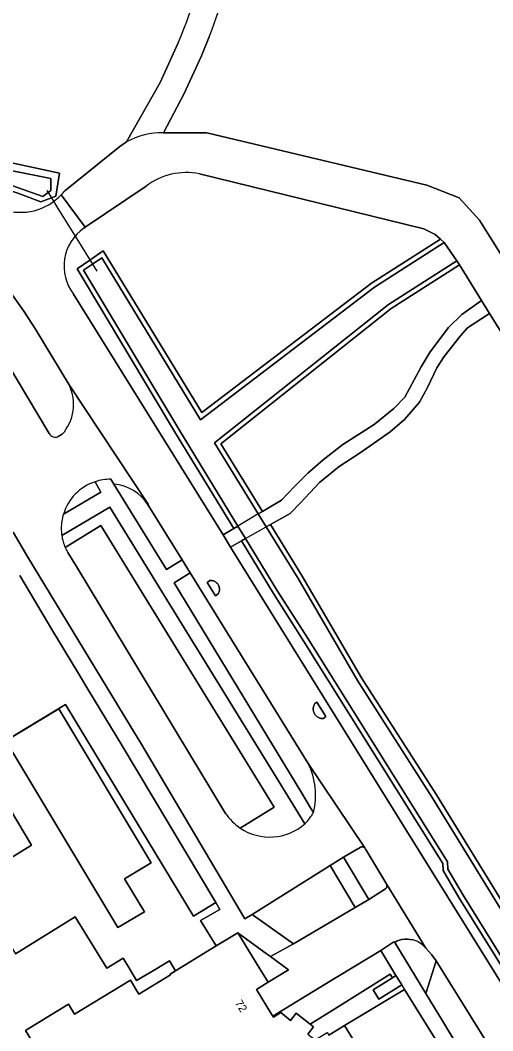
# Model space of a CAD drawing. Extents: x 158132 to 159664, y 385256 to 387218.
# Drawn here: x 158675.2 to 158734.3, y 386749.8 to 386876.1 of the extents above; entities that cross this region are included whole.
import ezdxf

# ---------------------------------------------------------------- set-up
doc = ezdxf.new("R2010")
doc.units = 0
for name, color, linetype in [('IMGEO_Berm_groen', 7, 'Continuous'), ('IMGEO_Dek', 7, 'Continuous'), ('IMGEO_Duiker', 7, 'Continuous'), ('IMGEO_Gemengd_bos', 7, 'Continuous'), ('IMGEO_Groenvoorziening', 7, 'Continuous'), ('IMGEO_Loofbos', 7, 'Continuous'), ('IMGEO_Oever', 7, 'Continuous'), ('IMGEO_Pand', 7, 'Continuous'), ('IMGEO_Pand_nummerreeks', 7, 'Continuous'), ('IMGEO_Parkeervlak_open', 7, 'Continuous'), ('IMGEO_Rijbaan_lokaal_gesloten', 7, 'Continuous'), ('IMGEO_Verkeerseiland_gesloten', 7, 'Continuous'), ('IMGEO_Voetpad_gesloten', 7, 'Continuous'), ('IMGEO_Voetpad_open', 7, 'Continuous'), ('IMGEO_Waterloop', 7, 'Continuous')]:
    doc.layers.add(name, color=color, linetype=linetype)

msp = doc.modelspace()

# ---------------------------------------------------------------- linework, layer by layer
at = {"layer": 'IMGEO_Berm_groen'}
msp.add_lwpolyline([(158718.49, 386772.28), (158718.35, 386772.52), (158718.33, 386772.55), (158718.32, 386772.58), (158718.3, 386772.61), (158718.28, 386772.65), (158718.25, 386772.67), (158718.23, 386772.7), (158718.2, 386772.72), (158718.17, 386772.74), (158718.14, 386772.76), (158718.11, 386772.78), (158718.07, 386772.79), (158718.04, 386772.8), (158718, 386772.81), (158717.96, 386772.81), (158717.93, 386772.81), (158717.89, 386772.81), (158717.85, 386772.8), (158717.82, 386772.79), (158717.78, 386772.78), (158717.75, 386772.76), (158717.72, 386772.74), (158717.69, 386772.72), (158715.6, 386771.51), (158718.77, 386766.24), (158720.86, 386767.56), (158720.89, 386767.59), (158720.92, 386767.62), (158720.94, 386767.65), (158720.96, 386767.68), (158720.98, 386767.72), (158721, 386767.75), (158721.01, 386767.79), (158721.02, 386767.83), (158721.02, 386767.87), (158721.03, 386767.91), (158721.03, 386767.95), (158721.02, 386767.99), (158721.01, 386768.03), (158721, 386768.07), (158720.99, 386768.1)], close=True, dxfattribs=at)
for points in [[(158724.29, 386761.18), (158723.94, 386761.23), (158723.6, 386761.26), (158723.25, 386761.26), (158722.83, 386761.21), (158722.58, 386761.15), (158722.28, 386761.04), (158722, 386760.84), (158725.88, 386754.49), (158727.18, 386758.58), (158726.58, 386759.37)], [(158726.58, 386759.37), (158725.88, 386760.15)]]:
    msp.add_lwpolyline(points, dxfattribs=at)
msp.add_arc((158723.16, 386757.71), 3.65, 41.8095, 71.8996, dxfattribs=at)
at = {"layer": 'IMGEO_Dek'}
msp.add_lwpolyline([(158702.4, 386812.87), (158703.36, 386811.3), (158705.94, 386812.76), (158704.94, 386814.39)], close=True, dxfattribs=at)
at = {"layer": 'IMGEO_Duiker'}
msp.add_lwpolyline([(158678.52, 386854.78), (158679.08, 386853.88), (158679.91, 386852.53), (158682.26, 386848.76), (158684.22, 386845.59), (158684.77, 386844.71)], dxfattribs=at)
at = {"layer": 'IMGEO_Gemengd_bos'}
for points in [[(158680.75, 386854.76), (158687.66, 386860.29), (158688.48, 386860.86), (158692.7, 386868.26), (158694.92, 386873.24)], [(158738.91, 386831.3), (158733.85, 386839.44), (158731.1, 386837.62), (158730.16, 386836.58), (158728.18, 386834.05), (158727.27, 386832.64), (158726.09, 386830.17), (158725.08, 386828.34), (158723.21, 386826.18), (158721.42, 386824.63), (158717.66, 386822.03), (158715.04, 386820.31), (158712.61, 386818.33), (158710.24, 386815.76), (158708.92, 386814.43), (158706.47, 386813.06), (158710.42, 386806.62), (158717.85, 386793.91), (158727.2, 386779.3), (158741.74, 386755.65)], [(158740.46, 386749.68), (158730.02, 386766.46), (158728.05, 386769.86), (158728, 386770.74), (158710.65, 386798.45), (158706.84, 386804.44), (158702.83, 386811.01), (158701.48, 386810.25), (158723.32, 386775.09), (158738.91, 386750), (158774.33, 386692.97)]]:
    msp.add_lwpolyline(points, dxfattribs=at)
for points in [[(158656.87, 386864.6), (158671.2, 386858.87), (158680.09, 386856.96), (158679.66, 386854.1), (158679.08, 386853.88), (158677.76, 386853.39), (158674.89, 386854.45), (158670.51, 386855.93), (158656.02, 386862.13), (158655.71, 386862.64), (158655.77, 386863.65)], [(158723.27, 386828.98), (158725.3, 386832.77), (158726.42, 386834.63), (158728.71, 386837.66), (158730.4, 386839.32), (158732.86, 386841.04), (158730.08, 386845.51), (158721.55, 386840.04), (158700.28, 386823.13), (158705.46, 386814.7), (158706.08, 386815.07), (158707.85, 386816.12), (158709.41, 386817.79), (158711.14, 386819.48), (158713.07, 386821.13), (158715.52, 386823.06), (158719.44, 386825.55), (158721.9, 386827.54)]]:
    msp.add_lwpolyline(points, close=True, dxfattribs=at)
for centre, radius, start, end in [((158644.17, 386895.43), 55.39, 336.384, 352.0933), ((158674.85, 386859.35), 7.48, 316.9831, 322.1116), ((158675.25, 386859.02), 6.96, 251.4012, 316.7563)]:
    msp.add_arc(centre, radius, start, end, dxfattribs=at)
at = {"layer": 'IMGEO_Groenvoorziening'}
for points in [[(158664.17, 386848.88), (158678.81, 386824.43)], [(158681.3, 386830.5), (158677.11, 386837.46), (158675.65, 386839.71), (158673.58, 386842.6)], [(158679.94, 386824.05), (158680.44, 386824.34)], [(158680.58, 386814.35), (158685.27, 386817.11), (158684.55, 386818.41)], [(158686.88, 386818.1), (158693.47, 386807.44), (158695.42, 386808.65), (158691.18, 386815.5)], [(158686.4, 386815.24), (158680.38, 386811.68)], [(158710.77, 386775.68), (158707.51, 386780.97), (158686.4, 386815.24)], [(158680.82, 386810.2), (158685.25, 386812.93), (158706.92, 386777.76), (158702.68, 386775.15)], [(158671.29, 386784.84), (158680.83, 386790.6), (158689.31, 386776.58), (158696.85, 386764.13), (158699.63, 386765.83), (158687.88, 386785.52), (158683.77, 386792.31), (158682.34, 386794.67), (158679.27, 386799.74), (158675.13, 386806.7)], [(158696.43, 386807.03), (158694.45, 386805.79), (158710.38, 386779.52), (158711.48, 386777.69), (158711.85, 386777.09)], [(158711.19, 386783.22), (158696.43, 386807.03)], [(158669.14, 386768.44), (158676.6, 386773.03), (158673.99, 386777.44)], [(158677.41, 386747.38), (158675.87, 386749.87), (158681.23, 386753.15), (158681.98, 386751.89), (158688.98, 386756.15), (158690.02, 386754.39), (158693.99, 386756.81), (158693.93, 386756.91), (158694.59, 386757.31), (158693.83, 386758.56), (158692.14, 386757.54), (158689.74, 386756.09), (158688.75, 386757.74), (158688.05, 386758.9), (158686.02, 386757.64), (158682.06, 386764.04), (158674.59, 386759.45)]]:
    msp.add_lwpolyline(points, dxfattribs=at)
for points in [[(158717.05, 386765.22), (158713.91, 386770.46), (158704.17, 386764.35), (158709.36, 386760.7)], [(158706.45, 386759.12), (158706.1, 386759.37), (158702.39, 386762.08), (158705.14, 386757.58), (158706.18, 386755.89), (158708.73, 386757.45), (158706.97, 386758.74)], [(158722.23, 386756.59), (158722.15, 386756.72), (158721.71, 386756.45), (158719.3, 386754.96), (158720.02, 386753.79), (158722.88, 386755.56)], [(158723.22, 386755), (158715.73, 386750.49), (158720.06, 386743.43), (158727.55, 386748.04)]]:
    msp.add_lwpolyline(points, close=True, dxfattribs=at)
for centre, radius, start, end in [((158676.28, 386828.06), 5.58, 318.1183, 25.8691), ((158679.58, 386824.83), 0.86, 207.4506, 295.0097), ((158686.47, 386812.58), 6.14, 108.1587, 163.2531), ((158686.47, 386812.58), 5.54, 31.7834, 85.7176), ((158685.87, 386812.5), 5.55, 188.4946, 204.4772), ((158702.97, 386779.24), 9.13, 346.3681, 25.7882), ((158706.38, 386780.66), 6.64, 236.1275, 311.4217)]:
    msp.add_arc(centre, radius, start, end, dxfattribs=at)
at = {"layer": 'IMGEO_Loofbos'}
for points in [[(158698.82, 386873.97), (158697.86, 386871.62), (158695.67, 386866.89), (158693.09, 386862), (158698.51, 386861.98), (158726.01, 386855.47), (158730.03, 386853.86), (158732.59, 386851.08), (158734.05, 386848.76), (158738.52, 386841.65)], [(158719.11, 386843.21), (158727.73, 386848.7), (158727.03, 386849.3), (158725.62, 386850), (158697.59, 386856.85)], [(158690.91, 386855.31), (158683.31, 386850.19), (158683.15, 386850.09)], [(158681.86, 386841.84), (158700.54, 386811.76), (158701.88, 386812.56), (158694.61, 386824.47), (158682.31, 386845.01), (158683.9, 386846.1), (158685.57, 386847.24), (158697.88, 386827.04), (158719.11, 386843.21)]]:
    msp.add_lwpolyline(points, dxfattribs=at)
for centre, radius, start, end in [((158642.89, 386896.04), 60.12, 338.462, 352.064), ((158695.9, 386848.92), 8.11, 78.0085, 128.0283), ((158686.4, 386845.35), 5.74, 124.4702, 217.7129)]:
    msp.add_arc(centre, radius, start, end, dxfattribs=at)
at = {"layer": 'IMGEO_Oever'}
for points in [[(158656.87, 386864.6), (158655.77, 386863.65), (158655.71, 386862.64), (158656.02, 386862.13), (158670.51, 386855.93), (158674.89, 386854.45), (158677.76, 386853.39), (158679.08, 386853.88), (158679.66, 386854.1), (158680.09, 386856.96), (158671.2, 386858.87)], [(158657.22, 386863.55), (158671.23, 386857.84), (158679, 386856.27), (158679, 386854.77), (158678.67, 386854.54), (158678.01, 386854.06), (158667.19, 386857.89), (158656.24, 386862.56), (158656.4, 386862.93), (158656.71, 386863.68)], [(158695.12, 386824.78), (158683.11, 386844.84), (158684.22, 386845.59), (158685.39, 386846.39), (158697.71, 386826.16), (158719.46, 386842.72), (158728.18, 386848.28), (158727.73, 386848.7), (158719.11, 386843.21), (158697.88, 386827.04), (158685.57, 386847.24), (158683.9, 386846.1), (158682.31, 386845.01), (158694.61, 386824.47), (158701.88, 386812.56), (158702.4, 386812.87)], [(158730.08, 386845.51), (158729.76, 386846.02), (158721.2, 386840.53), (158699.49, 386823.27), (158704.94, 386814.39), (158705.46, 386814.7), (158700.28, 386823.13), (158721.55, 386840.04)]]:
    msp.add_lwpolyline(points, close=True, dxfattribs=at)
for points in [[(158749.38, 386743.68), (158745.14, 386750.32), (158741.74, 386755.65), (158727.2, 386779.3), (158717.85, 386793.91), (158710.42, 386806.62), (158706.47, 386813.06), (158705.94, 386812.76), (158709.91, 386806.31), (158717.34, 386793.59), (158726.69, 386778.98), (158741.23, 386755.33), (158744.63, 386750), (158748.87, 386743.37)], [(158743.36, 386746.16), (158740.97, 386750), (158730.53, 386766.77), (158728.64, 386770.03), (158728.59, 386770.93), (158711.16, 386798.77), (158707.35, 386804.76), (158703.36, 386811.3), (158702.83, 386811.01), (158706.84, 386804.44), (158710.65, 386798.45), (158728, 386770.74), (158728.05, 386769.86), (158730.02, 386766.46), (158740.46, 386749.68)]]:
    msp.add_lwpolyline(points, dxfattribs=at)
at = {"layer": 'IMGEO_Pand'}
msp.add_lwpolyline([(158687.4, 386762.71), (158690.71, 386764.69), (158688.24, 386768.81), (158691.55, 386770.8), (158680, 386790.03), (158673.39, 386786.05)], close=True, dxfattribs=at)
for points in [[(158711.14, 386749.42), (158711.84, 386750.32), (158711.44, 386750.63), (158709.68, 386752.01), (158708.98, 386751.11), (158707.77, 386752.1), (158706.83, 386751.53), (158706.76, 386751.65), (158706.6, 386751.92), (158704.72, 386755), (158706.18, 386755.89), (158705.14, 386757.58), (158702.39, 386762.08), (158699.69, 386760.43), (158694.59, 386757.31), (158693.93, 386756.91), (158693.99, 386756.81), (158690.02, 386754.39), (158688.98, 386756.15), (158681.98, 386751.89), (158681.23, 386753.15), (158675.87, 386749.87), (158677.41, 386747.38)], [(158720.06, 386743.43), (158715.73, 386750.49), (158713.75, 386749.29)]]:
    msp.add_lwpolyline(points, dxfattribs=at)
at = {"layer": 'IMGEO_Parkeervlak_open'}
for points in [[(158738.52, 386841.65), (158734.05, 386848.76), (158732.59, 386851.08), (158730.03, 386853.86), (158726.01, 386855.47), (158698.51, 386861.98), (158693.09, 386862)], [(158688.48, 386860.86), (158687.66, 386860.29), (158680.75, 386854.76)], [(158697.59, 386856.85), (158725.62, 386850), (158727.03, 386849.3), (158727.73, 386848.7), (158728.18, 386848.28), (158729.76, 386846.02), (158730.08, 386845.51), (158732.86, 386841.04), (158733.85, 386839.44), (158738.91, 386831.3), (158764.91, 386790.32), (158766.78, 386787.69), (158768.37, 386786.88), (158770.04, 386785.73), (158786.68, 386759.23), (158796.45, 386743.69), (158814.08, 386715.63), (158817.59, 386717.84), (158779.74, 386777.99), (158774.03, 386787.05), (158804.8, 386806.61)], [(158680.32, 386854.25), (158683.31, 386850.19), (158690.91, 386855.31)], [(158702.68, 386775.15), (158706.92, 386777.76), (158685.25, 386812.93), (158680.82, 386810.2)], [(158681.16, 386809.57), (158682.21, 386807.82), (158700.86, 386776.97)]]:
    msp.add_lwpolyline(points, dxfattribs=at)
msp.add_lwpolyline([(158727.18, 386758.58), (158725.88, 386754.49), (158727.95, 386751.06), (158733.36, 386742.16), (158738.15, 386740.88), (158732.5, 386750)], close=True, dxfattribs=at)
for centre, radius, start, end in [((158692.92, 386852.84), 9.16, 88.9153, 118.9641), ((158695.9, 386848.92), 8.11, 78.0085, 128.0283), ((158674.85, 386859.35), 7.48, 316.9831, 322.1116), ((158686.23, 386812.71), 5.97, 204.8466, 211.7224), ((158706.39, 386780.67), 6.66, 213.7775, 236.0967)]:
    msp.add_arc(centre, radius, start, end, dxfattribs=at)
at = {"layer": 'IMGEO_Rijbaan_lokaal_gesloten'}
for points in [[(158678.81, 386824.43), (158664.17, 386848.88), (158656.73, 386859.94), (158655.38, 386860.52), (158653.1, 386861.53), (158630.22, 386871.36), (158627.88, 386872.37)], [(158683.15, 386850.09), (158683.31, 386850.19), (158680.32, 386854.25)], [(158673.58, 386842.6), (158675.65, 386839.71), (158677.11, 386837.46), (158681.3, 386830.5), (158691.18, 386815.6), (158691.18, 386815.5), (158695.42, 386808.65), (158696.43, 386807.03), (158711.19, 386783.22), (158718.25, 386772.67), (158718.28, 386772.65), (158718.3, 386772.61), (158718.32, 386772.58), (158718.33, 386772.55), (158718.35, 386772.52), (158718.49, 386772.28), (158720.99, 386768.1), (158725.88, 386760.15), (158726.58, 386759.37), (158727.18, 386758.58), (158732.5, 386750), (158738.15, 386740.88)], [(158774.33, 386692.97), (158738.91, 386750), (158723.32, 386775.09), (158701.48, 386810.25), (158700.54, 386811.76), (158681.86, 386841.84)], [(158691.18, 386815.5), (158691.18, 386815.6), (158681.3, 386830.5)], [(158680.44, 386824.34), (158679.94, 386824.05)], [(158686.5, 386818.72), (158686.88, 386818.1)], [(158674.32, 386812.09), (158676.14, 386809), (158689.49, 386787.04), (158690.28, 386785.75), (158703.28, 386763.8), (158704.17, 386764.35), (158713.91, 386770.46), (158715.6, 386771.51), (158717.69, 386772.72), (158717.72, 386772.74), (158717.75, 386772.76), (158717.78, 386772.78), (158717.82, 386772.79), (158717.85, 386772.8), (158717.89, 386772.81), (158717.93, 386772.81), (158717.96, 386772.81), (158718, 386772.81), (158718.04, 386772.8), (158718.07, 386772.79), (158718.11, 386772.78), (158718.14, 386772.76), (158718.17, 386772.74), (158718.2, 386772.72), (158718.23, 386772.7), (158718.25, 386772.67), (158711.19, 386783.22)], [(158682.21, 386807.82), (158681.16, 386809.57)], [(158700.86, 386776.97), (158682.21, 386807.82)], [(158720.99, 386768.1), (158721, 386768.07), (158721.01, 386768.03), (158721.02, 386767.99), (158721.03, 386767.95), (158721.03, 386767.91), (158721.02, 386767.87), (158721.02, 386767.83), (158721.01, 386767.79), (158721, 386767.75), (158720.98, 386767.72), (158720.96, 386767.68), (158720.94, 386767.65), (158720.92, 386767.62), (158720.89, 386767.59), (158720.86, 386767.56), (158718.77, 386766.24), (158718.57, 386766.11), (158717.05, 386765.22), (158709.36, 386760.7), (158706.45, 386759.12), (158706.97, 386758.74), (158708.73, 386757.45), (158706.18, 386755.89), (158704.72, 386755), (158706.6, 386751.92), (158706.76, 386751.65), (158713.29, 386755.64), (158720.25, 386759.85), (158721.88, 386760.92), (158721.92, 386760.9), (158721.95, 386760.88), (158721.96, 386760.87), (158722, 386760.84), (158722.28, 386761.04), (158722.58, 386761.15), (158722.83, 386761.21), (158723.25, 386761.26), (158723.6, 386761.26), (158723.94, 386761.23), (158724.29, 386761.18)], [(158725.88, 386760.15), (158720.99, 386768.1)]]:
    msp.add_lwpolyline(points, dxfattribs=at)
for points in [[(158698.89, 386806.08), (158698.99, 386806.08), (158699.08, 386806.08), (158699.18, 386806.07), (158699.27, 386806.05), (158699.36, 386806.02), (158699.45, 386805.98), (158699.53, 386805.94), (158699.61, 386805.89), (158699.69, 386805.84), (158699.76, 386805.78), (158699.82, 386805.71), (158699.88, 386805.64), (158699.93, 386805.56), (158699.98, 386805.48), (158700.02, 386805.39), (158700.05, 386805.3), (158700.07, 386805.21), (158700.09, 386805.12), (158700.1, 386805.03), (158700.09, 386804.93), (158700.09, 386804.84), (158700.07, 386804.74), (158700.05, 386804.65), (158700.01, 386804.57), (158699.97, 386804.48), (158699.93, 386804.4), (158699.58, 386804.15), (158698.54, 386805.82)], [(158712.02, 386790.7), (158712.28, 386790.86), (158713.4, 386789.1), (158713.08, 386788.84), (158712.98, 386788.83), (158712.87, 386788.84), (158712.77, 386788.85), (158712.67, 386788.88), (158712.57, 386788.91), (158712.48, 386788.95), (158712.39, 386789), (158712.3, 386789.05), (158712.22, 386789.12), (158712.15, 386789.19), (158712.08, 386789.26), (158712.02, 386789.35), (158711.96, 386789.43), (158711.92, 386789.53), (158711.88, 386789.62), (158711.85, 386789.72), (158711.83, 386789.82), (158711.81, 386789.92), (158711.81, 386790.02), (158711.81, 386790.13), (158711.83, 386790.23), (158711.85, 386790.33), (158711.88, 386790.42), (158711.92, 386790.52), (158711.97, 386790.61)]]:
    msp.add_lwpolyline(points, close=True, dxfattribs=at)
for centre, radius, start, end in [((158675.25, 386859.02), 6.96, 251.4012, 316.7563), ((158686.4, 386845.35), 5.74, 124.4702, 217.7129), ((158676.28, 386828.06), 5.58, 318.1183, 25.8691), ((158679.58, 386824.83), 0.86, 207.4506, 295.0097), ((158686.47, 386812.58), 6.14, 108.1587, 163.2531), ((158686.47, 386812.59), 6.13, 89.6608, 108.1758), ((158686.47, 386812.58), 5.54, 31.7834, 85.7176), ((158686.44, 386812.58), 6.12, 163.2017, 179.6786), ((158685.8, 386812.5), 5.48, 178.7755, 188.5757), ((158685.87, 386812.5), 5.55, 188.4946, 204.4772), ((158686.23, 386812.71), 5.97, 204.8466, 211.7224), ((158702.97, 386779.24), 9.13, 346.3681, 25.7882), ((158706.39, 386780.67), 6.66, 213.7775, 236.0967), ((158706.34, 386780.18), 6.31, 314.6123, 330.7553), ((158706.38, 386780.66), 6.64, 236.1275, 311.4217), ((158723.16, 386757.71), 3.65, 41.8095, 71.8996)]:
    msp.add_arc(centre, radius, start, end, dxfattribs=at)
at = {"layer": 'IMGEO_Verkeerseiland_gesloten'}
for points in [[(158698.89, 386806.08), (158698.54, 386805.82), (158699.58, 386804.15), (158699.93, 386804.4), (158699.97, 386804.48), (158700.01, 386804.57), (158700.05, 386804.65), (158700.07, 386804.74), (158700.09, 386804.84), (158700.09, 386804.93), (158700.1, 386805.03), (158700.09, 386805.12), (158700.07, 386805.21), (158700.05, 386805.3), (158700.02, 386805.39), (158699.98, 386805.48), (158699.93, 386805.56), (158699.88, 386805.64), (158699.82, 386805.71), (158699.76, 386805.78), (158699.69, 386805.84), (158699.61, 386805.89), (158699.53, 386805.94), (158699.45, 386805.98), (158699.36, 386806.02), (158699.27, 386806.05), (158699.18, 386806.07), (158699.08, 386806.08), (158698.99, 386806.08)], [(158712.02, 386790.7), (158711.97, 386790.61), (158711.92, 386790.52), (158711.88, 386790.42), (158711.85, 386790.33), (158711.83, 386790.23), (158711.81, 386790.13), (158711.81, 386790.02), (158711.81, 386789.92), (158711.83, 386789.82), (158711.85, 386789.72), (158711.88, 386789.62), (158711.92, 386789.53), (158711.96, 386789.43), (158712.02, 386789.35), (158712.08, 386789.26), (158712.15, 386789.19), (158712.22, 386789.12), (158712.3, 386789.05), (158712.39, 386789), (158712.48, 386788.95), (158712.57, 386788.91), (158712.67, 386788.88), (158712.77, 386788.85), (158712.87, 386788.84), (158712.98, 386788.83), (158713.08, 386788.84), (158713.4, 386789.1), (158712.28, 386790.86)]]:
    msp.add_lwpolyline(points, close=True, dxfattribs=at)
at = {"layer": 'IMGEO_Voetpad_gesloten'}
for points in [[(158705.94, 386812.76), (158704.94, 386814.39), (158702.4, 386812.87), (158703.36, 386811.3)], [(158721.43, 386756.88), (158721.71, 386756.45), (158722.15, 386756.72), (158720.25, 386759.85), (158713.29, 386755.64), (158706.76, 386751.65), (158706.83, 386751.53), (158707.77, 386752.1), (158708.98, 386751.11), (158709.68, 386752.01), (158711.44, 386750.63), (158714.19, 386752.35)]]:
    msp.add_lwpolyline(points, close=True, dxfattribs=at)
at = {"layer": 'IMGEO_Voetpad_open'}
for points in [[(158693.09, 386862), (158695.67, 386866.89), (158697.86, 386871.62), (158698.82, 386873.97)], [(158694.92, 386873.24), (158692.7, 386868.26), (158688.48, 386860.86)], [(158684.55, 386818.41), (158685.27, 386817.11), (158680.58, 386814.35)], [(158696.43, 386807.03), (158695.42, 386808.65), (158693.47, 386807.44), (158686.88, 386818.1), (158686.5, 386818.72)], [(158680.38, 386811.68), (158686.4, 386815.24), (158707.51, 386780.97), (158710.77, 386775.68)], [(158675.13, 386806.7), (158679.27, 386799.74), (158682.34, 386794.67), (158683.77, 386792.31), (158687.88, 386785.52), (158699.63, 386765.83), (158700.14, 386764.98), (158697.73, 386763.6), (158699.69, 386760.43), (158702.39, 386762.08), (158706.1, 386759.37), (158706.45, 386759.12), (158709.36, 386760.7), (158704.17, 386764.35), (158703.28, 386763.8), (158690.28, 386785.75), (158689.49, 386787.04), (158676.14, 386809), (158674.32, 386812.09)], [(158711.85, 386777.09), (158711.48, 386777.69), (158710.38, 386779.52), (158694.45, 386805.79), (158696.43, 386807.03)], [(158750.1, 386714.47), (158739.4, 386732.23), (158733.36, 386742.16), (158727.95, 386751.06), (158725.88, 386754.49), (158722, 386760.84), (158721.96, 386760.87), (158721.95, 386760.88), (158721.92, 386760.9), (158721.88, 386760.92), (158720.25, 386759.85), (158722.15, 386756.72), (158722.23, 386756.59), (158722.88, 386755.56), (158723.22, 386755), (158727.55, 386748.04), (158728.44, 386746.57), (158781.86, 386658.68)]]:
    msp.add_lwpolyline(points, dxfattribs=at)
for points in [[(158728.18, 386834.05), (158730.16, 386836.58), (158731.1, 386837.62), (158733.85, 386839.44), (158732.86, 386841.04), (158730.4, 386839.32), (158728.71, 386837.66), (158726.42, 386834.63), (158725.3, 386832.77), (158723.27, 386828.98), (158721.9, 386827.54), (158719.44, 386825.55), (158715.52, 386823.06), (158713.07, 386821.13), (158711.14, 386819.48), (158709.41, 386817.79), (158707.85, 386816.12), (158706.08, 386815.07), (158705.46, 386814.7), (158704.94, 386814.39), (158705.94, 386812.76), (158706.47, 386813.06), (158708.92, 386814.43), (158710.24, 386815.76), (158712.61, 386818.33), (158715.04, 386820.31), (158717.66, 386822.03), (158721.42, 386824.63), (158723.21, 386826.18), (158725.08, 386828.34), (158726.09, 386830.17), (158727.27, 386832.64)], [(158702.4, 386812.87), (158701.88, 386812.56), (158700.54, 386811.76), (158701.48, 386810.25), (158702.83, 386811.01), (158703.36, 386811.3)], [(158664.26, 386793.49), (158673.99, 386777.44), (158676.6, 386773.03), (158669.14, 386768.44), (158674.59, 386759.45), (158682.06, 386764.04), (158686.02, 386757.64), (158688.05, 386758.9), (158688.75, 386757.74), (158689.74, 386756.09), (158692.14, 386757.54), (158693.83, 386758.56), (158694.59, 386757.31), (158699.69, 386760.43), (158697.73, 386763.6), (158700.14, 386764.98), (158699.63, 386765.83), (158696.85, 386764.13), (158689.31, 386776.58), (158680.83, 386790.6), (158671.29, 386784.84), (158665.56, 386794.25)], [(158673.39, 386786.05), (158680, 386790.03), (158691.55, 386770.8), (158688.24, 386768.81), (158690.71, 386764.69), (158687.4, 386762.71)], [(158715.6, 386771.51), (158713.91, 386770.46), (158717.05, 386765.22), (158718.57, 386766.11), (158718.77, 386766.24)], [(158723.22, 386755), (158722.88, 386755.56), (158720.02, 386753.79), (158719.3, 386754.96), (158721.71, 386756.45), (158721.43, 386756.88), (158714.19, 386752.35), (158711.44, 386750.63), (158711.84, 386750.32), (158711.14, 386749.42), (158712.06, 386748.7), (158713.56, 386749.6), (158713.75, 386749.29), (158715.73, 386750.49)]]:
    msp.add_lwpolyline(points, close=True, dxfattribs=at)
for centre, radius, start, end in [((158644.17, 386895.43), 55.39, 336.384, 352.0933), ((158642.89, 386896.04), 60.12, 338.462, 352.064), ((158692.92, 386852.84), 9.16, 88.9153, 118.9641), ((158686.47, 386812.59), 6.13, 89.6608, 108.1758), ((158686.44, 386812.58), 6.12, 163.2017, 179.6786), ((158685.8, 386812.5), 5.48, 178.7755, 188.5757), ((158706.34, 386780.18), 6.31, 314.6123, 330.7553)]:
    msp.add_arc(centre, radius, start, end, dxfattribs=at)
at = {"layer": 'IMGEO_Waterloop'}
msp.add_lwpolyline([(158657.22, 386863.55), (158656.71, 386863.68), (158656.4, 386862.93), (158656.24, 386862.56), (158667.19, 386857.89), (158678.01, 386854.06), (158678.67, 386854.54), (158679, 386854.77), (158679, 386856.27), (158671.23, 386857.84)], close=True, dxfattribs=at)
msp.add_lwpolyline([(158741.23, 386755.33), (158726.69, 386778.98), (158717.34, 386793.59), (158709.91, 386806.31), (158705.94, 386812.76), (158704.94, 386814.39), (158699.49, 386823.27), (158721.2, 386840.53), (158729.76, 386846.02), (158728.18, 386848.28), (158719.46, 386842.72), (158697.71, 386826.16), (158685.39, 386846.39), (158684.22, 386845.59), (158683.11, 386844.84), (158695.12, 386824.78), (158702.4, 386812.87), (158703.36, 386811.3), (158707.35, 386804.76), (158711.16, 386798.77), (158728.59, 386770.93), (158728.64, 386770.03), (158730.53, 386766.77), (158740.97, 386750)], dxfattribs=at)

# ---------------------------------------------------------------- texts
at = {"layer": 'IMGEO_Pand_nummerreeks'}
msp.add_text('72', height=1, rotation=301.776, dxfattribs=at).set_placement((158701.99, 386753.3))

doc.saveas('drawing.dxf')
